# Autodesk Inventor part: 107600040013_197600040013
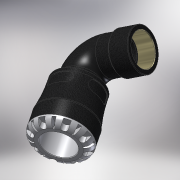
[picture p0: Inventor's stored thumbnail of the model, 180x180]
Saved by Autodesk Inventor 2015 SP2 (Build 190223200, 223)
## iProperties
Created: 2016-12
Part Number: 107600040013_197600040013
Material: PVC-Piping
Description: PLASSON 90° ELBOW WITH FEMALE INTEGRAL BRASS 40X1.1/4" SERIES 1
Document SubType Name: Modeling
Designer: KIM
Mass: 664.223 g
Surface Area: 733.008 cm^2
Volume: 474.445 cm^3
Density: 1.4 g/cm^3
Appearance: Black Cast
Author: KIM
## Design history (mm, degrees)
derived "1076.ipt"
feature "Solid1::1076.ipt"
tag "TaggingFeature1"
body "Solid1"
other parameters: "d1" = 30.24, "d8" = 61.6, "d13" = 8, "d14" = 8, "d15" = 0, "d17" = 360 deg, "d19" = 8 deg, "d20" = 0.8, "d21" = 0.8, "d22" = 8 deg, "d24" = 0, "d26" = 360 deg, "d33" = 7, "d51" = 0.7, "d54" = 14, "d55" = 8.8, "d57" = 15.68, "d58" = 0, "d74" = 0, "d78" = 72, "d82" = 0.8, "d115" = 360 deg, "d207" = 90 deg, "d228" = 11.9, "d248" = 4.32, "d270" = 107, "d279" = 67, "d281" = 5.8428, "d294" = 38.952, "d295" = 21, "d296" = 23.1, "d297" = 35.0568, "d299" = 45.57384, "d300" = 35.0568, "d301" = 0, "d302" = 0, "d306" = 2.53188, "d309" = 72.72, "d310" = 8.01308, "d312" = 15 deg, "d313" = 0.56, "d314" = 8.208, "d315" = 0.35, "l_" = 72, "A_" = 107, "A_1" = 67, "l_2" = 21, "Rp_" = 38.952, "d298" = 50.6376
